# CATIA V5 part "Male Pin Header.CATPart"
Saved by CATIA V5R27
Part number: Male Pin Header
Definition: Male Pin Header
Nomenclature: Male Pin Header v1
Source: Unknown
Bounding box of the stored display mesh (mm): x 0 to 2.54, y -6 to 5.54, z 0 to 2.54
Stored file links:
  E:\university\my-thesis\My Thesis Publication\Final-Updata\CAD\Male Pin Header.CATPart
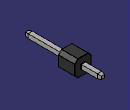
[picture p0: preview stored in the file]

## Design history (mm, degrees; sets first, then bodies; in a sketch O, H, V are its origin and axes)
Body1 "Body1" (main body)
  Solid1: solid without history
